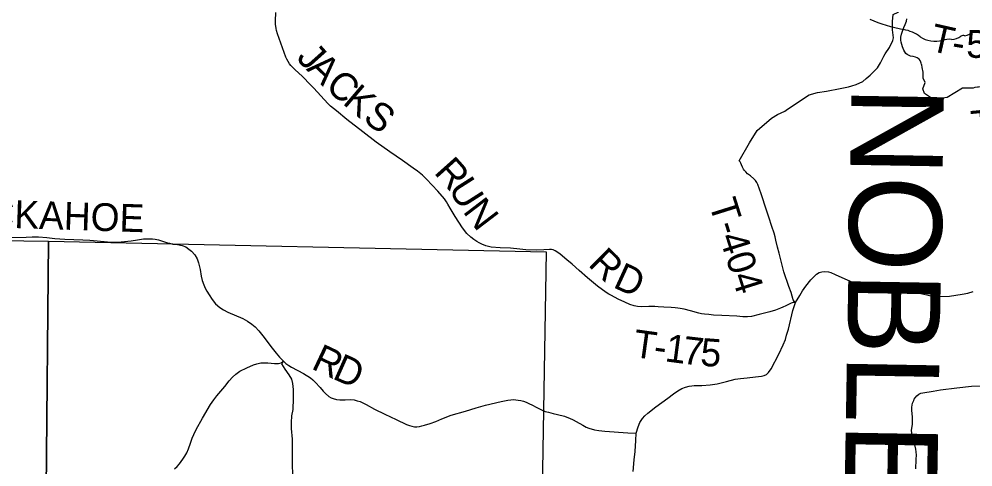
# Model space of a CAD drawing. Extents: x 0 to 34, y 0 to 22.
# Drawn here: x 5.085 to 7.038, y 18.013 to 18.929 of the extents above; entities that cross this region are included whole.
import ezdxf

# ---------------------------------------------------------------- set-up
doc = ezdxf.new("R2010")
doc.units = 0
for name, color, linetype in [('GM_X_Corporation', 7, 'Continuous'), ('GM_X_County_Road', 7, 'Continuous'), ('GM_X_County_Road_Text', 7, 'Continuous'), ('GM_X_County_Text', 7, 'Continuous'), ('GM_X_State_Route', 7, 'Continuous'), ('GM_X_State_Shield', 7, 'Continuous'), ('GM_X_Township_Road', 7, 'Continuous'), ('GM_X_Township_Road_Text', 7, 'Continuous')]:
    doc.layers.add(name, color=color, linetype=linetype)

msp = doc.modelspace()

# ---------------------------------------------------------------- linework, layer by layer
at = {"layer": 'GM_X_Corporation'}
for points in [[(4.1319, 18.4883), (5.1454, 18.4748), (5.1353, 17.4571), (4.1176, 17.4733)], [(5.1454, 18.4748), (6.1644, 18.4533), (6.147, 17.4393), (5.1353, 17.4571)]]:
    msp.add_lwpolyline(points, close=True, dxfattribs=at)
at = {"layer": 'GM_X_County_Road'}
msp.add_lwpolyline([(5.0692, 18.4821), (5.0991, 18.4833), (5.1119, 18.484), (5.1243, 18.4839), (5.1414, 18.4825), (5.1582, 18.4804), (5.1785, 18.479), (5.1972, 18.4784), (5.2152, 18.4776), (5.2295, 18.4767), (5.2446, 18.4758), (5.2658, 18.4737), (5.2753, 18.4731), (5.2868, 18.473), (5.3005, 18.4743), (5.3144, 18.4759), (5.3273, 18.4778), (5.3399, 18.4794), (5.3495, 18.48), (5.3578, 18.4797), (5.3632, 18.479), (5.3702, 18.4775), (5.3786, 18.4748), (5.387, 18.4721), (5.3928, 18.4705), (5.3998, 18.469), (5.4095, 18.4682), (5.419, 18.4661), (5.426, 18.4632), (5.4324, 18.4588), (5.4378, 18.4541), (5.445, 18.4468), (5.4494, 18.4389), (5.4522, 18.4305), (5.4554, 18.4171), (5.4578, 18.4035), (5.4599, 18.3945), (5.463, 18.3858), (5.466, 18.3788), (5.4693, 18.3726), (5.474, 18.3651), (5.48, 18.3558), (5.4873, 18.3468), (5.4958, 18.3392), (5.5032, 18.3341), (5.5125, 18.3299), (5.5428, 18.3168), (5.5524, 18.3114), (5.5617, 18.3048), (5.568, 18.2994), (5.5759, 18.2913), (5.587, 18.2775), (5.5943, 18.2674), (5.6029, 18.2559), (5.6114, 18.2458), (5.6182, 18.2378), (5.6262, 18.2292), (5.6314, 18.2244), (5.6371, 18.2205), (5.6428, 18.2173), (5.6672, 18.204), (5.6815, 18.1949), (5.6864, 18.1911), (5.6913, 18.1866), (5.7017, 18.1752), (5.7078, 18.1681), (5.7125, 18.163), (5.7194, 18.1569), (5.7236, 18.1544), (5.7278, 18.1529), (5.7345, 18.151), (5.7414, 18.1502), (5.7467, 18.1499), (5.7525, 18.15), (5.7635, 18.1507), (5.7709, 18.1501), (5.7772, 18.1484), (5.7832, 18.1464), (5.7957, 18.1407), (5.8127, 18.1312), (5.8337, 18.1208), (5.8572, 18.1101), (5.878, 18.0998), (5.8845, 18.0974), (5.8892, 18.0962), (5.8946, 18.0952), (5.8994, 18.0951), (5.9049, 18.0954), (5.9098, 18.0966), (5.9152, 18.0981), (5.9263, 18.1016), (5.9382, 18.1061), (5.9502, 18.1111), (5.9693, 18.1188), (5.9987, 18.1272), (6.0211, 18.1339), (6.0398, 18.1389), (6.0719, 18.1464), (6.0789, 18.1484), (6.0859, 18.1497), (6.0917, 18.1504), (6.0974, 18.1505), (6.102, 18.1502), (6.1067, 18.1495), (6.1121, 18.1485), (6.1177, 18.1472), (6.1232, 18.1454), (6.1289, 18.1429), (6.1362, 18.1395), (6.1436, 18.1353), (6.1562, 18.1287), (6.1618, 18.1264), (6.1686, 18.1246), (6.1786, 18.1225), (6.1876, 18.1204), (6.2019, 18.1166), (6.2068, 18.115), (6.212, 18.1128), (6.2194, 18.1095), (6.2259, 18.1057), (6.239, 18.0986), (6.2461, 18.0939), (6.2512, 18.0919), (6.2628, 18.0889), (6.2723, 18.0876), (6.2846, 18.0863), (6.3316, 18.0825), (6.3485, 18.0818)], dxfattribs=at)
at = {"layer": 'GM_X_State_Route'}
msp.add_lwpolyline([(6.3424, 18.0038), (6.3446, 18.0271), (6.3463, 18.0442), (6.3476, 18.0668), (6.3485, 18.0818), (6.3522, 18.0952), (6.3559, 18.1037), (6.3617, 18.1121), (6.3665, 18.1176), (6.3725, 18.1227), (6.3889, 18.1355), (6.413, 18.1533), (6.425, 18.1626), (6.4336, 18.1686), (6.4417, 18.1732), (6.4492, 18.1762), (6.457, 18.1784), (6.4624, 18.1791), (6.4673, 18.1794), (6.483, 18.1797), (6.5, 18.181), (6.5142, 18.1832), (6.5335, 18.188), (6.5514, 18.1922), (6.5623, 18.194), (6.5755, 18.1955), (6.593, 18.1969), (6.6053, 18.1983), (6.6105, 18.1997), (6.6155, 18.2022), (6.6194, 18.2058), (6.625, 18.2138), (6.6403, 18.2439), (6.6492, 18.2626), (6.6539, 18.2734), (6.6565, 18.2823), (6.6601, 18.2951), (6.6694, 18.3331), (6.6745, 18.3496), (6.6834, 18.364), (6.6891, 18.373), (6.6959, 18.3825), (6.7064, 18.3955), (6.7175, 18.4071), (6.7233, 18.4107), (6.7285, 18.4123), (6.7337, 18.4131), (6.7423, 18.4122), (6.7471, 18.4108), (6.7562, 18.4069), (6.7697, 18.4006), (6.7917, 18.3908), (6.8022, 18.3867), (6.8128, 18.383), (6.8245, 18.3805), (6.8433, 18.3783), (6.8756, 18.3752), (6.9046, 18.3723), (6.9182, 18.3706), (6.9311, 18.3678), (6.9439, 18.3649), (6.9544, 18.3626), (6.9649, 18.3614), (6.9903, 18.3623), (7.016, 18.3661), (7.0274, 18.3686), (7.0386, 18.3719)], dxfattribs=at)
at = {"layer": 'GM_X_State_Shield'}
for centre, major_axis, start_param, end_param in [((6.9516, 19.105), (0.2524, 0), 4.195997, 4.488961), ((6.8764, 18.8469), (0.079, 0), 0.823519, 1.323587), ((6.9618, 18.9242), (0.0501, 0), 4.026481, 4.996735), ((6.9908, 18.8551), (0.0412, 0), 1.495662, 1.94098), ((6.9944, 18.9093), (0.0267, 0), 4.691044, 5.507374), ((7.0186, 18.8899), (0.00752, 0), 1.147584, 2.315152), ((7.0154, 18.9174), (0.0282, 0), 4.937069, 5.64225)]:
    msp.add_ellipse(centre, major_axis=major_axis, ratio=0.8, start_param=start_param, end_param=end_param, dxfattribs=at)
at = {"layer": 'GM_X_Township_Road'}
for points in [[(6.8195, 18.8077), (6.8278, 18.8146), (6.8423, 18.8299), (6.849, 18.84), (6.8553, 18.8537), (6.8582, 18.8585), (6.8675, 18.8714), (6.8742, 18.8858), (6.8755, 18.8913), (6.873, 18.9075), (6.8733, 18.9245), (6.8748, 18.9387), (6.885, 18.9438), (6.8931, 18.9567)], [(6.6745, 18.3496), (6.6697, 18.3494), (6.6656, 18.3482), (6.6549, 18.3426), (6.6491, 18.3399), (6.6437, 18.3376), (6.6337, 18.3339), (6.622, 18.3304), (6.6109, 18.3274), (6.6, 18.3247), (6.5845, 18.321), (6.5761, 18.3199), (6.5668, 18.3202), (6.5548, 18.3211), (6.5242, 18.3228), (6.5071, 18.3237), (6.4972, 18.3246), (6.4887, 18.3255), (6.4822, 18.3264), (6.4767, 18.3278), (6.4596, 18.3323), (6.4465, 18.3355), (6.4388, 18.3371), (6.434, 18.338), (6.4285, 18.3386), (6.4201, 18.3389), (6.4049, 18.3395), (6.3938, 18.3406), (6.3867, 18.3411), (6.3747, 18.3411), (6.359, 18.3405), (6.3515, 18.341), (6.3441, 18.3427), (6.3358, 18.3454), (6.3252, 18.3498), (6.3115, 18.3563), (6.298, 18.3634), (6.2922, 18.3662), (6.2867, 18.3697), (6.2691, 18.3826), (6.2486, 18.3998), (6.2319, 18.4148), (6.2176, 18.4277), (6.2067, 18.4366), (6.193, 18.4485), (6.1863, 18.4534), (6.1828, 18.4554), (6.1784, 18.4569), (6.1748, 18.4576), (6.171, 18.4577), (6.1593, 18.4574), (6.1439, 18.4565), (6.1222, 18.4573), (6.1102, 18.4584), (6.0908, 18.4605), (6.0702, 18.4613), (6.0513, 18.4626), (6.0403, 18.4656), (6.0327, 18.4687), (6.0267, 18.4715), (6.022, 18.4745), (6.016, 18.4784), (6.0098, 18.4831), (6.002, 18.4907), (5.9928, 18.5025), (5.9851, 18.5141), (5.978, 18.5254), (5.9675, 18.5425), (5.9631, 18.5503), (5.96, 18.5555), (5.956, 18.5615), (5.9425, 18.5772), (5.9189, 18.6017), (5.9106, 18.6098), (5.901, 18.6179), (5.8921, 18.6245), (5.8698, 18.6399), (5.8443, 18.6577), (5.8161, 18.6778), (5.7887, 18.6987), (5.7561, 18.7242), (5.7349, 18.7415), (5.7225, 18.751), (5.7169, 18.7566), (5.7026, 18.7724), (5.6886, 18.788), (5.6824, 18.7945), (5.6644, 18.8127), (5.6504, 18.8256), (5.6415, 18.8342), (5.6386, 18.8381), (5.6357, 18.8423), (5.6328, 18.8475), (5.6309, 18.8515), (5.6274, 18.8612), (5.6206, 18.8802), (5.614, 18.899), (5.6121, 18.9058), (5.6112, 18.9099), (5.6097, 18.9191), (5.6097, 18.9261), (5.6105, 18.9428)], [(6.9329, 18.8366), (6.9323, 18.8389), (6.9316, 18.8412), (6.9301, 18.8445), (6.928, 18.8472), (6.9262, 18.8491), (6.9241, 18.8501), (6.9203, 18.8517), (6.9159, 18.8529), (6.91, 18.8538), (6.9059, 18.8553), (6.9032, 18.8569), (6.9007, 18.8592), (6.8986, 18.8624), (6.8966, 18.866), (6.8937, 18.8726), (6.8923, 18.8773), (6.8912, 18.8824), (6.8906, 18.8866), (6.8907, 18.8925), (6.892, 18.8984), (6.8937, 18.9044), (6.8966, 18.9125), (6.8992, 18.9181), (6.9017, 18.9249), (6.9029, 18.9303)], [(7.0538, 18.7907), (7.0492, 18.7901), (7.0477, 18.79), (7.0418, 18.7893), (7.0382, 18.7882), (7.0281, 18.7881), (7.0164, 18.7882), (6.9853, 18.769), (6.966, 18.7665), (6.9512, 18.7689), (6.939, 18.7774), (6.9354, 18.7868), (6.9404, 18.7998), (6.9361, 18.8087), (6.9363, 18.8145), (6.9361, 18.8207), (6.9344, 18.8302), (6.9331, 18.8358), (6.9329, 18.8366)], [(6.6583, 18.7448), (6.7029, 18.7747), (6.7196, 18.7789), (6.7382, 18.7822), (6.7665, 18.7876), (6.7831, 18.7911), (6.7898, 18.7926), (6.799, 18.7954), (6.8123, 18.8019), (6.8195, 18.8077)], [(6.6745, 18.3496), (6.6719, 18.3521), (6.6701, 18.3548), (6.6656, 18.3695), (6.6613, 18.3823), (6.6507, 18.4123), (6.6441, 18.4393), (6.6415, 18.4503), (6.6379, 18.4626), (6.6344, 18.4772), (6.633, 18.4841), (6.6307, 18.4916), (6.6264, 18.5048), (6.6198, 18.5239), (6.6154, 18.5381), (6.6046, 18.5719), (6.5976, 18.591), (6.5955, 18.5951), (6.593, 18.5988), (6.5896, 18.6024), (6.5827, 18.6083), (6.5767, 18.6129), (6.5727, 18.6165), (6.5705, 18.6192), (6.5682, 18.6226), (6.5662, 18.6264), (6.5644, 18.6311), (6.5627, 18.6347), (6.5611, 18.637), (6.5591, 18.6394), (6.5806, 18.6764), (6.5959, 18.7011), (6.6253, 18.7265), (6.6378, 18.734), (6.6531, 18.7413), (6.6583, 18.7448)], [(5.4032, 18.009), (5.4084, 18.0134), (5.4131, 18.0192), (5.4201, 18.0289), (5.4242, 18.0346), (5.4281, 18.0415), (5.432, 18.0502), (5.4357, 18.0615), (5.4395, 18.0718), (5.4426, 18.079), (5.4476, 18.0891), (5.4603, 18.1129), (5.4768, 18.1407), (5.4833, 18.1504), (5.4901, 18.1585), (5.5059, 18.1777), (5.5148, 18.1891), (5.5217, 18.1963), (5.5288, 18.203), (5.5367, 18.2085), (5.5512, 18.2159), (5.5648, 18.2216), (5.572, 18.2241), (5.58, 18.2258), (5.5944, 18.2258), (5.6081, 18.2246), (5.6162, 18.2243), (5.6215, 18.2257), (5.6262, 18.2292)], [(5.6457, 17.9985), (5.6446, 18.0161), (5.6445, 18.0385), (5.6448, 18.05), (5.6448, 18.0621), (5.6445, 18.0697), (5.6429, 18.0917), (5.6425, 18.1037), (5.6435, 18.1171), (5.6459, 18.1301), (5.6468, 18.1527), (5.6469, 18.1715), (5.6455, 18.1835), (5.6435, 18.1923), (5.6377, 18.2011), (5.6296, 18.213), (5.6229, 18.2239), (5.6262, 18.2292)], [(6.9208, 18.009), (6.9219, 18.0283), (6.9225, 18.0374), (6.9219, 18.0432), (6.921, 18.0499), (6.9144, 18.0762), (6.9129, 18.0828), (6.9124, 18.0876), (6.9127, 18.0925), (6.914, 18.0996), (6.9145, 18.1106), (6.9143, 18.1153), (6.9136, 18.1216), (6.9126, 18.1288), (6.9127, 18.135), (6.9146, 18.1436), (6.9167, 18.1488), (6.918, 18.1515), (6.9196, 18.1543), (6.9232, 18.1586), (6.9274, 18.1618), (6.9313, 18.1636), (6.9353, 18.1648), (6.9569, 18.168), (6.9719, 18.1704), (7.005, 18.1746), (7.0354, 18.1778), (7.053, 18.179)]]:
    msp.add_lwpolyline(points, dxfattribs=at)

# ---------------------------------------------------------------- texts
at = {"layer": 'GM_X_County_Road_Text'}
for s, height, rotation, p in [('TUCKAHOE', 0.05682, 358.1241, (4.9184, 18.5069)), ('R', 0.0568, 334.7843, (5.6811, 18.2148)), ('D', 0.0568, 335.969, (5.7244, 18.1944))]:
    msp.add_text(s, height=height, rotation=rotation, dxfattribs=at).set_placement(p)
at = {"layer": 'GM_X_County_Text'}
msp.add_text('NOBLE COUNTY', height=0.189394, rotation=269.0214, dxfattribs=at).set_placement((6.7895, 18.7934))
at = {"layer": 'GM_X_Township_Road_Text'}
for s, height, rotation, p in [('T', 0.0568, 347.1384, (6.9472, 18.8654)), ('5', 0.0568, 358.6139, (7.0239, 18.8506)), ('J', 0.0568, 311.7674, (5.651, 18.8491)), ('-', 0.0568, 350.6353, (6.9923, 18.8552)), ('A', 0.0568, 315.2962, (5.6714, 18.8264)), ('C', 0.0568, 318.6059, (5.7095, 18.7888)), ('K', 0.0568, 319.6153, (5.7454, 18.7572)), ('S', 0.0568, 323.4722, (5.7867, 18.7222)), ('T', 0.0568, 5.3473, (7.0366, 18.6846)), ('R', 0.0568, 311.7444, (5.9328, 18.6149)), ('U', 0.0568, 302.417, (5.9624, 18.5821)), ('N', 0.0568, 307.3655, (5.9922, 18.5356)), ('T-404', 0.05682, 287.4332, (6.4968, 18.5522)), ('R', 0.0568, 315.5133, (6.2484, 18.426)), ('D', 0.0568, 335.336, (6.2989, 18.3814)), ('T', 0.0568, 352.0893, (6.34, 18.2383)), ('1', 0.0568, 352.5077, (6.4057, 18.2292)), ('7', 0.0568, 353.359, (6.4413, 18.2245)), ('5', 0.0568, 355.6513, (6.4786, 18.2203)), ('-', 0.0568, 352.1762, (6.3822, 18.2324))]:
    msp.add_text(s, height=height, rotation=rotation, dxfattribs=at).set_placement(p)

doc.saveas('drawing.dxf')
